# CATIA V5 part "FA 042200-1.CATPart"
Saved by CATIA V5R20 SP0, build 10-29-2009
Part number: FA 042200-1
Revision: ANY
Definition: UNKNOWN
Nomenclature: FA 042200-1
Source: Unknown
Bounding box of the stored display mesh (mm): x 0.374 to 3.8, y -1.58 to 1.58, z -1.58 to 1.58
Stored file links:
  C:\Users\Utente\Desktop\IO LAVORO\3D X SITO CF\CUMSA\3D files FA\FA 0422SF\FA 042200-1.CATPart

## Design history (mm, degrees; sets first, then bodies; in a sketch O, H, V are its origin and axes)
Body1 "Cortar-Extruir2" (main body)
  Solid1: solid without history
